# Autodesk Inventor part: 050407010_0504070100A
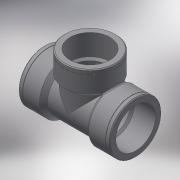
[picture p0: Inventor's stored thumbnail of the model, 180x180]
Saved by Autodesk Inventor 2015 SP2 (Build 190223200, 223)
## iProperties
Created: 2017-05
Part Number: 050407010_0504070100A
Material: Generic
Description: PLASSON THREADED TEE 1"
Document SubType Name: Modeling
Designer: KIM
Density: 1 g/cm^3
Appearance: Default
Author: KIM
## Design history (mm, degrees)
derived "050407.ipt"
feature "Solid1::050407.ipt"
tag "TaggingFeature1"
body "Solid1"
other parameters: "d0" = 40.5, "d2" = 0.5, "d3" = 0.5, "d4" = 39.3783, "d5" = 30.291, "d6" = 21, "d7" = 135 deg, "d8" = 24.15, "d9" = 4.025, "d19" = 0.60582, "d27" = 21, "d30" = 27.2619, "d31" = 33.3201, "d33" = 180 deg, "d39" = 0, "d45" = 0, "d46" = 33.3201, "d48" = 0, "d50" = 0, "d51" = 0.90873, "Rp_" = 30.291, "H_" = 81, "l_2" = 21
